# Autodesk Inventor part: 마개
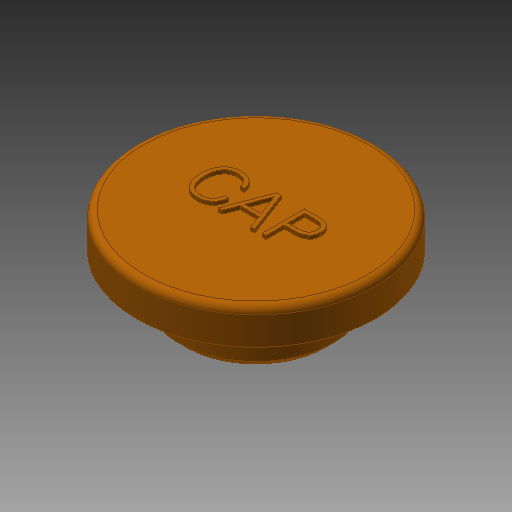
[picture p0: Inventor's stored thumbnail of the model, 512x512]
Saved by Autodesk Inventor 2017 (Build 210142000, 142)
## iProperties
Created: 2018-03
Part Number: 마개
Material: 고무
Document SubType Name: Modeling
Designer: mduedu
Density: 1 g/cm^3
Appearance: 주황색
Author: mduedu
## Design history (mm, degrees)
sketch "스케치1"
  geometry: C1 r 17 at (0, 0); 1 further point
  constraints: 1 centre point, 1 coincident
  dimensions: "d21" = 34 diameter of C1
extrude "돌출1" new body sketch "스케치1" distance "d2" = 6; taper "d3" = 0 deg
fillet "모깎기4" dims "d22" = 1
sketch "스케치6"
  geometry: C1 r 11 at (0, 0); 1 further point
  constraints: 1 centre point, 1 coincident
  dimensions: "d23" = 22 diameter of C1
extrude "돌출5" join sketch "스케치6" distance "d24" = 6; taper "d25" = 0 deg
sketch "스케치7"
  geometry: C1 r 7.5 at (0, 0); 1 further point
  constraints: 1 centre point, 1 coincident
  dimensions: "d26" = 15 diameter of C1
extrude "돌출6" cut sketch "스케치7" distance "d27" = 6; taper "d28" = 0 deg
sketch "스케치8"
  geometry: C1 r 17 at (0, 0) reference; C2 r 14 at (0, 0); 1 further point
  constraints: 1 centre point, 1 coincident
  dimensions: "d37" = 28 diameter of C2
extrude "돌출7" cut sketch "스케치8" distance "d30" = 1; taper "d31" = 0 deg
fillet "모깎기5" dims "d32" = 1
chamfer "모따기2" distance "d33" = 1; stored, may be unused: second distance "d34" = 2, angle "d35" = 45 deg
sketch "스케치5"
  geometry: 2 further points
  constraints: 1 coincident, 1 other
feature "엠보싱1" sketch "스케치5" dims "d19" = 0.5, "d20" = 0
node "솔리드1"
